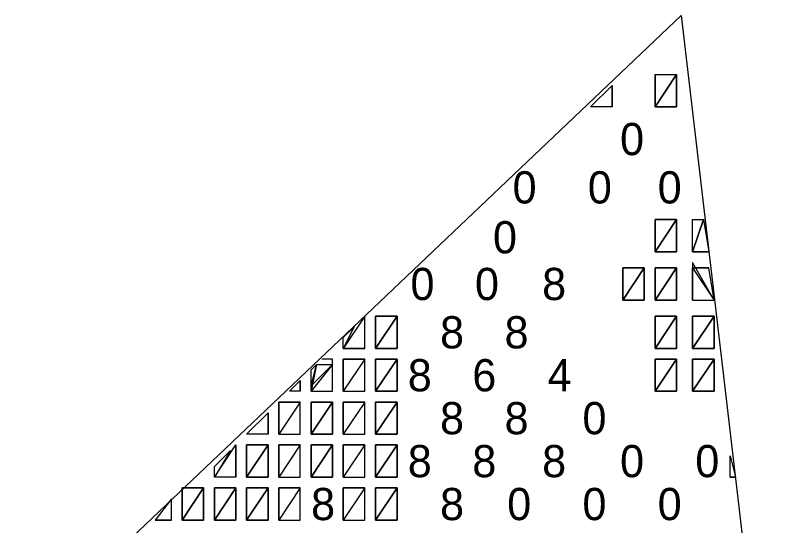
# Model space of a CAD drawing. Extents: x -10 to 89.7, y -4.8 to 22.
# Drawn here: x 2.2987 to 2.7095, y 1.7377 to 2.0081 of the extents above; entities that cross this region are included whole.
import ezdxf

# ---------------------------------------------------------------- set-up
doc = ezdxf.new("R2010")
doc.units = 0
doc.layers.add('Default', color=7, linetype='Continuous')

msp = doc.modelspace()

# ---------------------------------------------------------------- linework, layer by layer
at = {"layer": 'Default'}
for p, q in [((2.65109, 2.00807), (2.28801, 1.66263)), ((2.65109, 2.00807), (2.70953, 1.5109)), ((2.63727, 1.97673), (2.63727, 1.95966)), ((2.64865, 1.95966), (2.64865, 1.97673)), ((2.61451, 1.95966), (2.61451, 1.97104)), ((2.61451, 1.95966), (2.60313, 1.95966)), ((2.63727, 1.95966), (2.64865, 1.95966)), ((2.64865, 1.89991), (2.63727, 1.89991)), ((2.63727, 1.89991), (2.63727, 1.88284)), ((2.64865, 1.88284), (2.64865, 1.89991)), ((2.65719, 1.89991), (2.66288, 1.89991)), ((2.65719, 1.88284), (2.65719, 1.89991)), ((2.63727, 1.88284), (2.64865, 1.88284)), ((2.65719, 1.88284), (2.66572, 1.88284)), ((2.63158, 1.8743), (2.6202, 1.8743)), ((2.6202, 1.8743), (2.6202, 1.85723)), ((2.63158, 1.85723), (2.63158, 1.8743)), ((2.63727, 1.8743), (2.63727, 1.85723)), ((2.64865, 1.8743), (2.63727, 1.8743)), ((2.64865, 1.85723), (2.64865, 1.8743)), ((2.65719, 1.8743), (2.66572, 1.8743)), ((2.65719, 1.85723), (2.65719, 1.8743)), ((2.6202, 1.85723), (2.63158, 1.85723)), ((2.63727, 1.85723), (2.64865, 1.85723)), ((2.65719, 1.85723), (2.66857, 1.85723)), ((2.48363, 1.83162), (2.48363, 1.84869)), ((2.48932, 1.84869), (2.48932, 1.83162)), ((2.5007, 1.84869), (2.48932, 1.84869)), ((2.5007, 1.83162), (2.5007, 1.84869)), ((2.64865, 1.84869), (2.63727, 1.84869)), ((2.63727, 1.84869), (2.63727, 1.83162)), ((2.64865, 1.83162), (2.64865, 1.84869)), ((2.66857, 1.84869), (2.65719, 1.84869)), ((2.65719, 1.84869), (2.65719, 1.83162)), ((2.66857, 1.83162), (2.66857, 1.84869)), ((2.47225, 1.83162), (2.47225, 1.83731)), ((2.48363, 1.83162), (2.47225, 1.83162)), ((2.48932, 1.83162), (2.5007, 1.83162)), ((2.63727, 1.83162), (2.64865, 1.83162)), ((2.65719, 1.83162), (2.66857, 1.83162)), ((2.46656, 1.82593), (2.46087, 1.82593)), ((2.46656, 1.80886), (2.46656, 1.82593)), ((2.48363, 1.82593), (2.47225, 1.82593)), ((2.47225, 1.82593), (2.47225, 1.80886)), ((2.48363, 1.80886), (2.48363, 1.82593)), ((2.5007, 1.82593), (2.48932, 1.82593)), ((2.48932, 1.82593), (2.48932, 1.80886)), ((2.5007, 1.80886), (2.5007, 1.82593)), ((2.63727, 1.82593), (2.63727, 1.80886)), ((2.64865, 1.82593), (2.63727, 1.82593)), ((2.64865, 1.80886), (2.64865, 1.82593)), ((2.65719, 1.82593), (2.65719, 1.80886)), ((2.66857, 1.82593), (2.65719, 1.82593)), ((2.66857, 1.80886), (2.66857, 1.82593)), ((2.45518, 1.80886), (2.45518, 1.82024)), ((2.44949, 1.80886), (2.44949, 1.81455)), ((2.44949, 1.80886), (2.4438, 1.80886)), ((2.45518, 1.80886), (2.46656, 1.80886)), ((2.47225, 1.80886), (2.48363, 1.80886)), ((2.48932, 1.80886), (2.5007, 1.80886)), ((2.63727, 1.80886), (2.64865, 1.80886)), ((2.65719, 1.80886), (2.66857, 1.80886)), ((2.44949, 1.80317), (2.43811, 1.80317)), ((2.43811, 1.80317), (2.43811, 1.7861)), ((2.44949, 1.7861), (2.44949, 1.80317)), ((2.45518, 1.80317), (2.45518, 1.7861)), ((2.46656, 1.80317), (2.45518, 1.80317)), ((2.46656, 1.7861), (2.46656, 1.80317)), ((2.48363, 1.80317), (2.47225, 1.80317)), ((2.47225, 1.80317), (2.47225, 1.7861)), ((2.48363, 1.7861), (2.48363, 1.80317)), ((2.5007, 1.80317), (2.48932, 1.80317)), ((2.48932, 1.80317), (2.48932, 1.7861)), ((2.5007, 1.7861), (2.5007, 1.80317)), ((2.43242, 1.7861), (2.43242, 1.79748)), ((2.43242, 1.7861), (2.42104, 1.7861)), ((2.43811, 1.7861), (2.44949, 1.7861)), ((2.45518, 1.7861), (2.46656, 1.7861)), ((2.47225, 1.7861), (2.48363, 1.7861)), ((2.48932, 1.7861), (2.5007, 1.7861)), ((2.41535, 1.76334), (2.41535, 1.78041)), ((2.43242, 1.78041), (2.42104, 1.78041)), ((2.42104, 1.78041), (2.42104, 1.76334)), ((2.43242, 1.76334), (2.43242, 1.78041)), ((2.44949, 1.78041), (2.43811, 1.78041)), ((2.43811, 1.78041), (2.43811, 1.76334)), ((2.44949, 1.76334), (2.44949, 1.78041)), ((2.46656, 1.78041), (2.45518, 1.78041)), ((2.45518, 1.78041), (2.45518, 1.76334)), ((2.46656, 1.76334), (2.46656, 1.78041)), ((2.48363, 1.78041), (2.47225, 1.78041)), ((2.47225, 1.78041), (2.47225, 1.76334)), ((2.48363, 1.76334), (2.48363, 1.78041)), ((2.5007, 1.78041), (2.48932, 1.78041)), ((2.48932, 1.78041), (2.48932, 1.76334)), ((2.5007, 1.76334), (2.5007, 1.78041)), ((2.67711, 1.76334), (2.67711, 1.77472)), ((2.41535, 1.76334), (2.40397, 1.76334)), ((2.42104, 1.76334), (2.43242, 1.76334)), ((2.43811, 1.76334), (2.44949, 1.76334)), ((2.45518, 1.76334), (2.46656, 1.76334)), ((2.47225, 1.76334), (2.48363, 1.76334)), ((2.48932, 1.76334), (2.5007, 1.76334)), ((2.67711, 1.76334), (2.67995, 1.76334)), ((2.3869, 1.75765), (2.3869, 1.74058)), ((2.39828, 1.75765), (2.3869, 1.75765)), ((2.39828, 1.74058), (2.39828, 1.75765)), ((2.41535, 1.75765), (2.40397, 1.75765)), ((2.40397, 1.75765), (2.40397, 1.74058)), ((2.41535, 1.74058), (2.41535, 1.75765)), ((2.42104, 1.75765), (2.42104, 1.74058)), ((2.43242, 1.75765), (2.42104, 1.75765)), ((2.43242, 1.74058), (2.43242, 1.75765)), ((2.44949, 1.75765), (2.43811, 1.75765)), ((2.43811, 1.75765), (2.43811, 1.74058)), ((2.44949, 1.74058), (2.44949, 1.75765)), ((2.48363, 1.75765), (2.47225, 1.75765)), ((2.47225, 1.75765), (2.47225, 1.74058)), ((2.48363, 1.74058), (2.48363, 1.75765)), ((2.5007, 1.75765), (2.48932, 1.75765)), ((2.48932, 1.75765), (2.48932, 1.74058)), ((2.5007, 1.74058), (2.5007, 1.75765)), ((2.38121, 1.74058), (2.38121, 1.75196)), ((2.38121, 1.74058), (2.37267, 1.74058)), ((2.3869, 1.74058), (2.39828, 1.74058)), ((2.40397, 1.74058), (2.41535, 1.74058)), ((2.42104, 1.74058), (2.43242, 1.74058)), ((2.43811, 1.74058), (2.44949, 1.74058)), ((2.47225, 1.74058), (2.48363, 1.74058)), ((2.48932, 1.74058), (2.5007, 1.74058))]:
    msp.add_line(p, q, dxfattribs=at)
for points in [[(2.64865, 1.97673), (2.64865, 1.95966), (2.63727, 1.95966)], [(2.63727, 1.95966), (2.63727, 1.97673), (2.64865, 1.97673)], [(2.60313, 1.95966), (2.61451, 1.97104), (2.61451, 1.95966)], [(2.63727, 1.88284), (2.63727, 1.89991), (2.64865, 1.89991)], [(2.64865, 1.89991), (2.64865, 1.88284), (2.63727, 1.88284)], [(2.65719, 1.88284), (2.65719, 1.89991), (2.66288, 1.89991)], [(2.66572, 1.88284), (2.65719, 1.88284), (2.66288, 1.89991)], [(2.6202, 1.85723), (2.6202, 1.8743), (2.63158, 1.8743)], [(2.63158, 1.8743), (2.63158, 1.85723), (2.6202, 1.85723)], [(2.64865, 1.8743), (2.64865, 1.85723), (2.63727, 1.85723)], [(2.63727, 1.85723), (2.63727, 1.8743), (2.64865, 1.8743)], [(2.65719, 1.87715), (2.65719, 1.85723), (2.66857, 1.85723)], [(2.66857, 1.85723), (2.66572, 1.8743), (2.65719, 1.8743)], [(2.47225, 1.83162), (2.48363, 1.83162), (2.48363, 1.84869)], [(2.5007, 1.84869), (2.5007, 1.83162), (2.48932, 1.83162)], [(2.48932, 1.83162), (2.48932, 1.84869), (2.5007, 1.84869)], [(2.63727, 1.83162), (2.63727, 1.84869), (2.64865, 1.84869)], [(2.64865, 1.84869), (2.64865, 1.83162), (2.63727, 1.83162)], [(2.65719, 1.83162), (2.65719, 1.84869), (2.66857, 1.84869)], [(2.66857, 1.84869), (2.66857, 1.83162), (2.65719, 1.83162)], [(2.47225, 1.83162), (2.47225, 1.83731), (2.47794, 1.843)], [(2.47225, 1.80886), (2.48363, 1.80886), (2.48363, 1.82593)], [(2.47225, 1.80886), (2.47225, 1.82593), (2.48363, 1.82593)], [(2.48932, 1.80886), (2.48932, 1.82593), (2.5007, 1.82593)], [(2.5007, 1.82593), (2.5007, 1.80886), (2.48932, 1.80886)], [(2.64865, 1.82593), (2.64865, 1.80886), (2.63727, 1.80886)], [(2.63727, 1.80886), (2.63727, 1.82593), (2.64865, 1.82593)], [(2.66857, 1.82593), (2.66857, 1.80886), (2.65719, 1.80886)], [(2.65719, 1.80886), (2.65719, 1.82593), (2.66857, 1.82593)], [(2.45518, 1.81171), (2.45803, 1.82309), (2.46656, 1.82309)], [(2.45803, 1.82309), (2.45803, 1.82309), (2.45518, 1.81171)], [(2.45518, 1.80886), (2.45518, 1.82024), (2.45803, 1.82309)], [(2.45518, 1.80886), (2.46656, 1.80886), (2.46656, 1.82309)], [(2.4438, 1.80886), (2.44949, 1.81455), (2.44949, 1.80886)], [(2.43811, 1.7861), (2.44949, 1.7861), (2.44949, 1.80317)], [(2.43811, 1.7861), (2.43811, 1.80317), (2.44949, 1.80317)], [(2.46656, 1.80317), (2.46656, 1.7861), (2.45518, 1.7861)], [(2.45518, 1.7861), (2.45518, 1.80317), (2.46656, 1.80317)], [(2.47225, 1.7861), (2.48363, 1.7861), (2.48363, 1.80317)], [(2.47225, 1.7861), (2.47225, 1.80317), (2.48363, 1.80317)], [(2.48932, 1.7861), (2.48932, 1.80317), (2.5007, 1.80317)], [(2.5007, 1.80317), (2.5007, 1.7861), (2.48932, 1.7861)], [(2.42104, 1.7861), (2.43242, 1.79748), (2.43242, 1.7861)], [(2.40397, 1.76334), (2.41535, 1.78041), (2.41535, 1.76334)], [(2.43242, 1.78041), (2.43242, 1.76334), (2.42104, 1.76334)], [(2.42104, 1.76334), (2.42104, 1.78041), (2.43242, 1.78041)], [(2.43811, 1.76334), (2.44949, 1.76334), (2.44949, 1.78041)], [(2.43811, 1.76334), (2.43811, 1.78041), (2.44949, 1.78041)], [(2.46656, 1.78041), (2.46656, 1.76334), (2.45518, 1.76334)], [(2.45518, 1.76334), (2.45518, 1.78041), (2.46656, 1.78041)], [(2.47225, 1.76334), (2.48363, 1.76334), (2.48363, 1.78041)], [(2.47225, 1.76334), (2.47225, 1.78041), (2.48363, 1.78041)], [(2.48932, 1.76334), (2.48932, 1.78041), (2.5007, 1.78041)], [(2.5007, 1.78041), (2.5007, 1.76334), (2.48932, 1.76334)], [(2.40397, 1.76334), (2.40397, 1.76903), (2.4125, 1.77756)], [(2.67995, 1.76334), (2.67711, 1.76334), (2.67711, 1.77472)], [(2.3869, 1.74058), (2.3869, 1.75765), (2.39828, 1.75765)], [(2.39828, 1.75765), (2.39828, 1.74058), (2.3869, 1.74058)], [(2.39828, 1.75765), (2.39828, 1.75765), (2.39828, 1.75765)], [(2.40397, 1.74058), (2.40397, 1.75765), (2.41535, 1.75765)], [(2.41535, 1.75765), (2.41535, 1.74058), (2.40397, 1.74058)], [(2.43242, 1.75765), (2.43242, 1.74058), (2.42104, 1.74058)], [(2.42104, 1.74058), (2.42104, 1.75765), (2.43242, 1.75765)], [(2.43811, 1.74058), (2.44949, 1.74058), (2.44949, 1.75765)], [(2.43811, 1.74058), (2.43811, 1.75765), (2.44949, 1.75765)], [(2.47225, 1.74058), (2.48363, 1.74058), (2.48363, 1.75765)], [(2.47225, 1.74058), (2.47225, 1.75765), (2.48363, 1.75765)], [(2.48932, 1.74058), (2.48932, 1.75765), (2.5007, 1.75765)], [(2.5007, 1.75765), (2.5007, 1.74058), (2.48932, 1.74058)], [(2.37267, 1.74058), (2.38121, 1.74058), (2.38121, 1.75196)]]:
    msp.add_lwpolyline(points, close=True, dxfattribs=at)

# ---------------------------------------------------------------- texts
for s, p in [('0', (2.61878, 1.93405)), ('0', (2.56188, 1.90844)), ('0', (2.60171, 1.90844)), ('0', (2.6387, 1.90844)), ('0', (2.5515, 1.882)), ('0', (2.50782, 1.85723)), ('0', (2.54196, 1.85723)), ('8', (2.57752, 1.85723)), ('8', (2.52347, 1.83162)), ('8', (2.55761, 1.83162)), ('8', (2.50639, 1.80886)), ('6', (2.54054, 1.80886)), ('4', (2.58037, 1.80886)), ('8', (2.52347, 1.7861)), ('8', (2.55761, 1.7861)), ('0', (2.59886, 1.7861)), ('8', (2.50639, 1.76334)), ('8', (2.54054, 1.76334)), ('8', (2.57752, 1.76334)), ('0', (2.61878, 1.76334)), ('0', (2.65861, 1.76334)), ('8', (2.45518, 1.74058)), ('8', (2.52347, 1.74058)), ('0', (2.55903, 1.74058)), ('0', (2.59886, 1.74058)), ('0', (2.6387, 1.74058))]:
    msp.add_text(s, height=0.01707, dxfattribs=at).set_placement(p)

doc.saveas('drawing.dxf')
